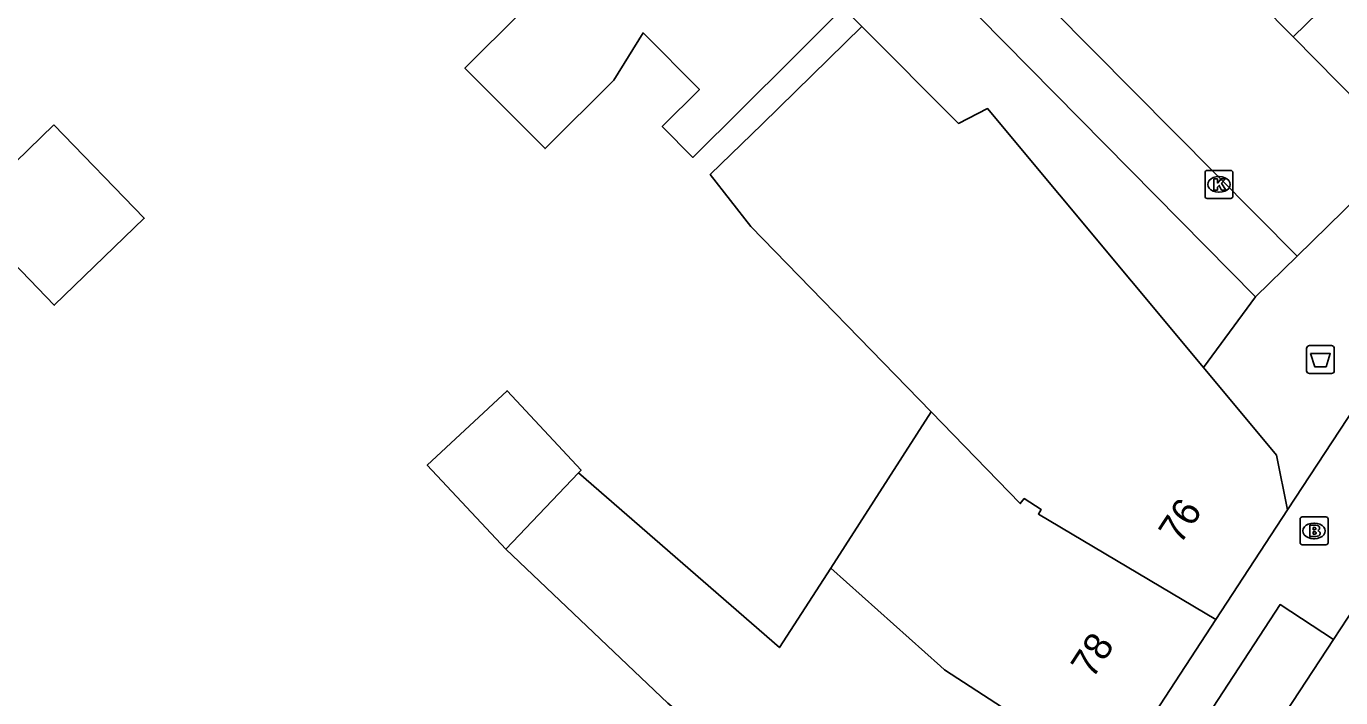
# Model space of a CAD drawing. Extents: x 160107 to 160928, y 382056 to 382918.
# Drawn here: x 160782.84 to 160829.99, y 382664.5 to 382688.58 of the extents above; entities that cross this region are included whole.
import ezdxf

# ---------------------------------------------------------------- set-up
doc = ezdxf.new("R2010")
doc.units = 0
for name, color, linetype in [('IMGEO_Afvalbak', 7, 'Continuous'), ('IMGEO_Brandkraan', 7, 'Continuous'), ('IMGEO_Kolk', 7, 'Continuous'), ('IMGEO_Pand', 7, 'Continuous'), ('IMGEO_Pand_nummerreeks', 7, 'Continuous'), ('IMGEO_Rijbaan_lokaal_gesloten', 7, 'Continuous'), ('IMGEO_Rijbaan_lokaal_open', 7, 'Continuous'), ('IMGEO_Voetpad_open', 7, 'Continuous')]:
    doc.layers.add(name, color=color, linetype=linetype)

msp = doc.modelspace()

# ---------------------------------------------------------------- linework, layer by layer
at = {"layer": 'IMGEO_Afvalbak'}
for p, q in [((160828.765, 382676.224), (160828.765, 382677.024)), ((160828.765, 382677.024), (160828.765, 382676.224)), ((160828.865, 382677.124), (160829.655, 382677.124)), ((160829.655, 382677.124), (160828.865, 382677.124)), ((160829.755, 382677.024), (160829.755, 382676.224)), ((160829.755, 382676.224), (160829.755, 382677.024)), ((160829.655, 382676.124), (160828.865, 382676.124)), ((160828.865, 382676.124), (160829.655, 382676.124))]:
    msp.add_line(p, q, dxfattribs=at)
msp.add_lwpolyline([(160828.908, 382676.838), (160829.612, 382676.838), (160829.463, 382676.368), (160829.057, 382676.368), (160828.908, 382676.838)], dxfattribs=at)
for centre, start, end in [((160828.865, 382677.024), 90, 180), ((160828.865, 382677.024), 90, 180), ((160829.655, 382677.024), 0, 90), ((160829.655, 382677.024), 360, 90), ((160828.865, 382676.224), 180, 270), ((160828.865, 382676.224), 180, 270), ((160829.655, 382676.224), 270, 0), ((160829.655, 382676.224), 270, 0)]:
    msp.add_arc(centre, 0.1, start, end, dxfattribs=at)
at = {"layer": 'IMGEO_Brandkraan'}
for p, q in [((160828.53, 382670.056), (160828.53, 382670.908)), ((160828.605, 382670.982), (160829.457, 382670.982)), ((160829.018, 382670.762), (160829.043, 382670.762)), ((160829.531, 382670.908), (160829.531, 382670.056)), ((160829.041, 382670.202), (160829.016, 382670.202)), ((160829.457, 382669.982), (160828.605, 382669.982))]:
    msp.add_line(p, q, dxfattribs=at)
for points in [[(160828.53, 382670.056), (160828.53, 382670.908)], [(160828.605, 382670.982), (160829.457, 382670.982)], [(160828.878, 382670.682), (160828.878, 382670.282), (160829.091, 382670.282)], [(160829.109, 382670.682), (160828.878, 382670.682)], [(160829.531, 382670.908), (160829.531, 382670.056)], [(160829.057, 382670.601), (160829.003, 382670.601), (160829.003, 382670.525)], [(160829.003, 382670.525), (160829.056, 382670.525)], [(160829.065, 382670.449), (160829.003, 382670.449), (160829.003, 382670.368)], [(160829.003, 382670.368), (160829.065, 382670.368)], [(160829.457, 382669.982), (160828.605, 382669.982)]]:
    msp.add_lwpolyline(points, dxfattribs=at)
for centre, radius, start, end in [((160828.607, 382670.906), 0.0765, 91.552, 178.448), ((160828.607, 382670.906), 0.0765, 91.552, 178.448), ((160829.113, 382670.537), 0.145, 59.4692, 91.5367), ((160829.138, 382670.584), 0.0922, 285.5137, 58.1501), ((160829.455, 382670.906), 0.0765, 1.552, 88.448), ((160829.455, 382670.906), 0.0765, 1.552, 88.448), ((160829.058, 382670.563), 0.0379, 267.8285, 90.9355), ((160829.066, 382670.408), 0.0404, 269.8759, 90.5077), ((160829.097, 382670.533), 0.251, 268.6676, 293.5347), ((160829.143, 382670.392), 0.105, 301.3115, 78.989), ((160828.607, 382670.058), 0.0765, 181.552, 268.448), ((160828.607, 382670.058), 0.0765, 181.552, 268.448), ((160829.455, 382670.058), 0.0765, 271.552, 358.448), ((160829.455, 382670.058), 0.0765, 271.552, 358.448)]:
    msp.add_arc(centre, radius, start, end, dxfattribs=at)
for centre, major_axis, ratio, start_param, end_param in [((160829.017, 382670.482), (-0.387, 0.002), 0.722429, 4.712389, 7.853982), ((160829.042, 382670.482), (-0.39, 0.002), 0.717154, 1.570796, 4.712389)]:
    msp.add_ellipse(centre, major_axis=major_axis, ratio=ratio, start_param=start_param, end_param=end_param, dxfattribs=at)
at = {"layer": 'IMGEO_Kolk'}
for p, q in [((160825.194, 382683.405), (160826.046, 382683.405)), ((160825.119, 382682.479), (160825.119, 382683.331)), ((160825.607, 382683.185), (160825.632, 382683.185)), ((160826.12, 382683.331), (160826.12, 382682.479)), ((160825.63, 382682.625), (160825.605, 382682.625)), ((160826.046, 382682.405), (160825.194, 382682.405))]:
    msp.add_line(p, q, dxfattribs=at)
for points in [[(160825.194, 382683.405), (160826.046, 382683.405)], [(160825.119, 382682.479), (160825.119, 382683.331)], [(160825.44, 382683.105), (160825.563, 382683.105), (160825.563, 382682.954), (160825.693, 382683.105), (160825.857, 382683.105), (160825.711, 382682.954), (160825.864, 382682.705), (160825.712, 382682.705), (160825.627, 382682.869), (160825.563, 382682.802), (160825.563, 382682.705), (160825.44, 382682.705), (160825.44, 382683.105)], [(160826.12, 382683.331), (160826.12, 382682.479)], [(160826.046, 382682.405), (160825.194, 382682.405)]]:
    msp.add_lwpolyline(points, dxfattribs=at)
for centre, start, end in [((160825.196, 382683.329), 91.552, 178.448), ((160825.196, 382683.329), 91.552, 178.448), ((160826.044, 382683.329), 1.552, 88.448), ((160826.044, 382683.329), 1.552, 88.448), ((160825.196, 382682.481), 181.552, 268.448), ((160825.196, 382682.481), 181.552, 268.448), ((160826.044, 382682.481), 271.552, 358.448), ((160826.044, 382682.481), 271.552, 358.448)]:
    msp.add_arc(centre, 0.0765, start, end, dxfattribs=at)
for centre, major_axis, ratio, start_param, end_param in [((160825.606, 382682.905), (-0.387, 0.002), 0.722429, 4.712389, 7.853982), ((160825.631, 382682.905), (-0.39, 0.002), 0.717154, 1.570796, 4.712389)]:
    msp.add_ellipse(centre, major_axis=major_axis, ratio=ratio, start_param=start_param, end_param=end_param, dxfattribs=at)
at = {"layer": 'IMGEO_Pand'}
for points in [[(160812.145, 382689.243), (160810.27, 382687.376), (160806.751, 382683.872), (160805.649, 382684.98), (160806.982, 382686.307), (160804.962, 382688.336), (160803.909, 382686.641), (160801.448, 382684.19), (160798.572, 382687.079), (160804.595, 382693.076), (160808.138, 382696.603)], [(160815.298, 382674.747), (160808.833, 382681.399), (160807.37, 382683.256), (160809.229, 382685.072), (160812.805, 382688.565)], [(160812.805, 382688.565), (160816.282, 382685.092), (160817.318, 382685.624), (160825.065, 382676.344)], [(160783.828, 382685.04), (160787.066, 382681.691), (160783.843, 382678.575), (160780.606, 382681.923), (160783.828, 382685.04)], [(160828.076, 382671.233), (160827.689, 382673.202), (160825.065, 382676.344)], [(160800.044, 382669.827), (160797.221, 382672.841), (160800.082, 382675.507), (160802.737, 382672.659), (160802.642, 382672.559)], [(160811.692, 382669.149), (160815.298, 382674.747)], [(160815.298, 382674.747), (160818.489, 382671.463), (160818.637, 382671.639), (160819.247, 382671.247), (160819.142, 382671.084), (160825.508, 382667.307)], [(160800.044, 382669.827), (160802.642, 382672.559)], [(160802.642, 382672.559), (160809.855, 382666.296), (160811.692, 382669.149)], [(160828.076, 382671.233), (160825.508, 382667.307)], [(160809.226, 382661.801), (160807.624, 382662.832), (160805.852, 382664.303), (160800.044, 382669.827)], [(160821.774, 382661.597), (160815.776, 382665.498), (160815.629, 382665.629), (160811.692, 382669.149)], [(160825.508, 382667.307), (160823.328, 382663.975), (160821.871, 382661.747), (160821.774, 382661.597)]]:
    msp.add_lwpolyline(points, dxfattribs=at)
at = {"layer": 'IMGEO_Rijbaan_lokaal_gesloten'}
for points in [[(160850.227, 382700.029), (160839.541, 382682.417), (160830.982, 382668.497), (160829.732, 382666.583)], [(160829.732, 382666.583), (160819.446, 382650.913)]]:
    msp.add_lwpolyline(points, dxfattribs=at)
at = {"layer": 'IMGEO_Rijbaan_lokaal_open'}
for points in [[(160828.283, 382688.201), (160823.394, 382693.141)], [(160816.679, 382692.183), (160828.426, 382680.337)], [(160828.426, 382680.337), (160832.296, 382684.125), (160828.283, 382688.201)]]:
    msp.add_lwpolyline(points, dxfattribs=at)
at = {"layer": 'IMGEO_Voetpad_open'}
for points in [[(160826.925, 382678.87), (160815.21, 382690.76), (160816.679, 382692.183)], [(160829.618, 382689.503), (160828.283, 382688.201)], [(160812.805, 382688.565), (160812.145, 382689.243)], [(160835.861, 382683.078), (160828.076, 382671.233)], [(160828.426, 382680.337), (160826.925, 382678.87)], [(160825.065, 382676.344), (160826.925, 382678.87)], [(160819.446, 382650.913), (160817.594, 382652.178), (160827.814, 382667.842), (160829.732, 382666.583)]]:
    msp.add_lwpolyline(points, dxfattribs=at)

# ---------------------------------------------------------------- texts
at = {"layer": 'IMGEO_Pand_nummerreeks'}
for s, rotation, p in [('76', 56.8088, (160824.23, 382669.959)), ('78', 56.8186, (160821.082, 382665.142))]:
    msp.add_text(s, height=1, rotation=rotation, dxfattribs=at).set_placement(p)

doc.saveas('drawing.dxf')
